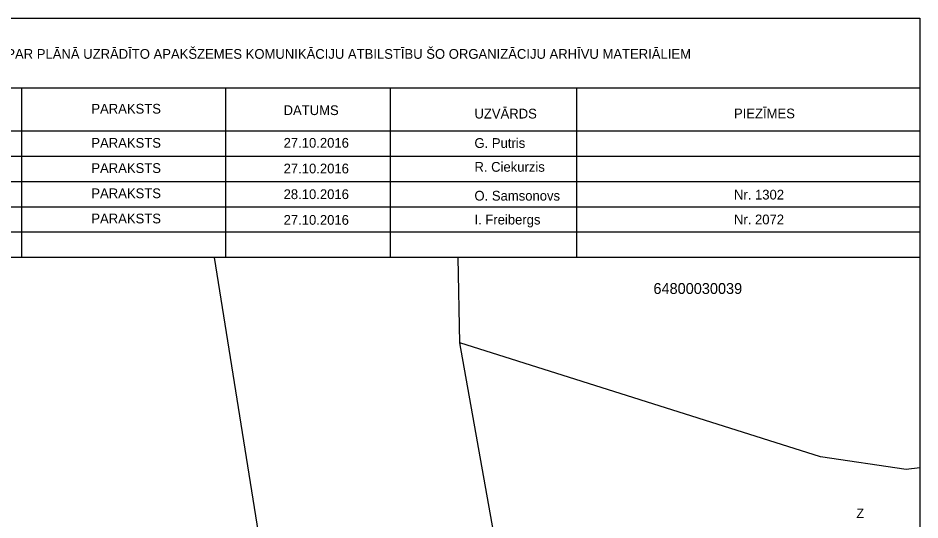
# Model space of a CAD drawing. Extents: x 321079 to 321220, y 257030 to 257220.
# Drawn here: x 321135.2 to 321218.3, y 257173.6 to 257219.9 of the extents above; entities that cross this region are included whole.
import ezdxf

# ---------------------------------------------------------------- set-up
doc = ezdxf.new("R2010")
doc.units = 0
for name, color, linetype in [('RAMI_PLAN_####_TKST_#', 7, 'Continuous'), ('ROBZ_KADS_####_TKST_#', 7, 'Continuous'), ('ROBZ_UZMR_####_####_#', 7, 'Continuous')]:
    doc.layers.add(name, color=color, linetype=linetype)

msp = doc.modelspace()

# ---------------------------------------------------------------- linework, layer by layer
at = {"layer": 'RAMI_PLAN_####_TKST_#'}
for p, q in [((321218.314, 257213.399), (321079.019, 257213.399)), ((321135.473, 257213.399), (321135.472, 257197.779)), ((321154.291, 257213.399), (321154.291, 257197.779)), ((321169.478, 257213.399), (321169.478, 257197.779)), ((321186.646, 257213.399), (321186.645, 257197.779)), ((321218.314, 257209.425), (321079.019, 257209.425)), ((321218.314, 257207.096), (321079.019, 257207.096)), ((321218.314, 257204.767), (321079.019, 257204.767)), ((321218.314, 257202.438), (321079.019, 257202.438)), ((321218.314, 257200.107), (321079.019, 257200.107)), ((321218.314, 257197.779), (321079.019, 257197.779))]:
    msp.add_line(p, q, dxfattribs=at)
msp.add_lwpolyline([(321079.019, 257029.866), (321079.019, 257219.866), (321218.314, 257219.866), (321218.314, 257029.866)], close=True, dxfattribs=at)
at = {"layer": 'ROBZ_UZMR_####_####_#'}
for p, q in [((321160.832, 257150.36), (321153.272, 257197.779)), ((321175.886, 257189.92), (321175.734, 257197.779)), ((321209.13, 257179.398), (321175.886, 257189.92)), ((321182.887, 257150.703), (321175.886, 257189.92)), ((321217.039, 257178.238), (321209.13, 257179.398)), ((321218.314, 257178.369), (321217.039, 257178.238))]:
    msp.add_line(p, q, dxfattribs=at)

# ---------------------------------------------------------------- texts
at = {"layer": 'RAMI_PLAN_####_TKST_#'}
for s, p in [('EKSPLUATĒJOŠO ORGANIZĀCIJU APLIECINĀJUMS PAR PLĀNĀ UZRĀDĪTO APAKŠZEMES KOMUNIKĀCIJU ATBILSTĪBU ŠO ORGANIZĀCIJU ARHĪVU MATERIĀLIEM', (321104.18, 257216.106)), ('PARAKSTS', (321141.913, 257211.049)), ('DATUMS', (321159.639, 257210.917)), ('UZVĀRDS', (321177.237, 257210.6)), ('PIEZĪMES', (321201.166, 257210.614)), ('PARAKSTS', (321141.913, 257207.904)), ('27.10.2016', (321159.639, 257207.907)), ('G. Putris', (321177.237, 257207.887)), ('R. Ciekurzis', (321177.237, 257205.69)), ('PARAKSTS', (321141.913, 257205.578)), ('27.10.2016', (321159.639, 257205.538)), ('PARAKSTS', (321141.913, 257203.253)), ('28.10.2016', (321159.639, 257203.169)), ('O. Samsonovs', (321177.237, 257203.028)), ('Nr. 1302', (321201.166, 257203.127)), ('PARAKSTS', (321141.913, 257200.927)), ('27.10.2016', (321159.639, 257200.8)), ('I. Freibergs', (321177.237, 257200.826)), ('Nr. 2072', (321201.166, 257200.84))]:
    msp.add_text(s, height=0.9, dxfattribs=at).set_placement(p)
msp.add_text('Z', height=0.878, rotation=360, dxfattribs=at).set_placement((321212.446, 257173.746))
at = {"layer": 'ROBZ_KADS_####_TKST_#'}
msp.add_text('64800030039', height=1, dxfattribs=at).set_placement((321193.74, 257194.421))

doc.saveas('drawing.dxf')
